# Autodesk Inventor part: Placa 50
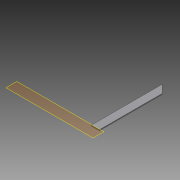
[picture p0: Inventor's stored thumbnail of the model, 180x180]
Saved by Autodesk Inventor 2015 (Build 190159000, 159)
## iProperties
Created: 2015-04
Part Number: Placa 50
Material: Generic
Document SubType Name: Modeling
Designer: suporte
Density: 1 g/cm^3
Appearance: Default
Author: suporte
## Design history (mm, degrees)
workplane "Work Plane1"
sketch "Sketch1"
  geometry: L1 (118.362, 1237.5)-(400, 956.058) reference; L2 (400, 956.058)-(400, 755) reference; L3 (400, 37.5)-(-500, 37.5) reference; L4 (-500, -62.5)-(500, -62.5) reference; L5 (400, 956.058)-(500, 856.128); L6 (500, 856.128)-(500, -50.202); L7 (500, 755)-(500, 180) reference; L8 (500, -50.202)-(500, -62.5); L9 (500, -62.5)-(400, -62.5); L10 (400, -62.5)-(400, 956.058); L11 (-500, -62.5)-(500, -62.5) reference; L12 (500, -62.5)-(500, 62.5) reference; L13 (500, 62.5)-(-500, 62.5) reference; L14 (-500, 62.5)-(-500, -62.5) reference; L15 (400, 62.5)-(500, 62.5); L16 (500, 62.5)-(500, 856.128); L17 (400, 62.5)-(400, 956.058); 2 further points
  constraints: 16 end point, 4 point on line, 2 collinear, 2 perpendicular, 2 vertical, 1 midpoint
extrude "Extrusion1" new body sketch "Sketch1" distance "d0" = 12.5; taper "d1" = 0 deg
body "Solid1"
node "Reference1"
node "Reference2"
node "Reference3"
node "Reference4"
node "Reference5"
node "Reference6"
